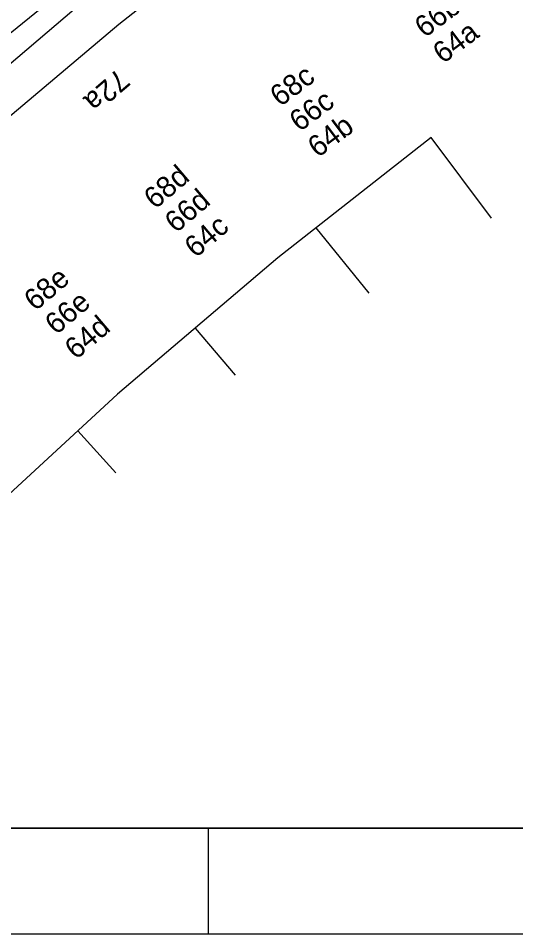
# Model space of a CAD drawing. Extents: x 81065 to 81486, y 452384 to 452681.
# Drawn here: x 81161.34 to 81184.88, y 452383.53 to 452426.85 of the extents above; entities that cross this region are included whole.
import ezdxf

# ---------------------------------------------------------------- set-up
doc = ezdxf.new("R2010")
doc.units = 0
for name, color, linetype in [('B-BH-AL-TOPOGRAFIE_HUISNUMMER-T25', 7, 'Continuous'), ('B-BH-OG-TERREIN_ERF-GV', 7, 'Continuous'), ('B-BH-OG-TOPOGRAFIE_BEBOUWING-GV', 7, 'Continuous'), ('B-BH-VH-KANTOPSLUITING-GV', 7, 'Continuous'), ('X-XX-AL-TEKENBLAD_KADER-G', 7, 'Continuous'), ('X-XX-AL-TEKENBLAD_KADER_AFSNIJMARKERING-G', 7, 'Continuous'), ('X-XX-AL-TEKENBLAD_KADER_VOUWMERK-G', 7, 'Continuous'), ('X-XX-AL-TEKENBLAD_VIEWPORT-G', 7, 'Continuous')]:
    doc.layers.add(name, color=color, linetype=linetype)

msp = doc.modelspace()

# ---------------------------------------------------------------- linework, layer by layer
at = {"layer": 'B-BH-OG-TERREIN_ERF-GV'}
for p, q in [((81177.939, 452413.843), (81175.442, 452416.944)), ((81169.709, 452412.189), (81171.601, 452409.957)), ((81165.948, 452405.341), (81164.153, 452407.332))]:
    msp.add_line(p, q, dxfattribs=at)
at = {"layer": 'B-BH-OG-TOPOGRAFIE_BEBOUWING-GV'}
msp.add_line((81183.742, 452417.4), (81180.883, 452421.217), dxfattribs=at)
for points in [[(81126.018, 452388.532), (81127.195, 452390.075), (81135.264, 452399.653), (81142.254, 452407.263), (81142.332, 452407.331), (81145.191, 452410.261), (81152.12, 452416.954), (81156.495, 452420.925), (81163.982, 452427.288), (81169.073, 452431.334), (81177.002, 452437.212), (81179.582, 452438.967)], [(81153.251, 452396.796), (81151.969, 452398.03), (81148.503, 452394.479), (81139.858, 452400.091), (81144.562, 452405.184), (81143.704, 452406.025), (81150.532, 452412.867), (81157.636, 452419.422), (81158.509, 452420.19), (81166.091, 452426.576), (81171.032, 452430.467), (81180.823, 452437.684), (81181.948, 452438.481)], [(81180.883, 452421.217), (81173.621, 452415.514), (81166.038, 452409.069), (81160.256, 452403.741), (81153.266, 452396.81), (81153.251, 452396.796)]]:
    msp.add_lwpolyline(points, dxfattribs=at)
at = {"layer": 'B-BH-VH-KANTOPSLUITING-GV'}
msp.add_lwpolyline([(81143.534, 452410.094), (81147.299, 452413.851), (81154.435, 452420.535), (81160.019, 452425.401), (81167.617, 452431.556), (81172.763, 452435.453), (81178.135, 452439.264)], dxfattribs=at)
at = {"layer": 'X-XX-AL-TEKENBLAD_KADER-G'}
msp.add_lwpolyline([(81480.708, 452388.532), (81070.22, 452388.532), (81070.22, 452675.532), (81480.708, 452675.532)], close=True, dxfattribs=at)
at = {"layer": 'X-XX-AL-TEKENBLAD_KADER_AFSNIJMARKERING-G'}
msp.add_lwpolyline([(81485.714, 452680.532), (81065.214, 452680.532), (81065.214, 452383.532), (81485.714, 452383.532)], close=True, dxfattribs=at)
at = {"layer": 'X-XX-AL-TEKENBLAD_KADER_VOUWMERK-G'}
msp.add_line((81170.339, 452383.532), (81170.339, 452388.532), dxfattribs=at)
at = {"layer": 'X-XX-AL-TEKENBLAD_VIEWPORT-G'}
msp.add_lwpolyline([(81070.22, 452388.532), (81480.708, 452388.532), (81480.708, 452675.532), (81070.22, 452675.532)], close=True, dxfattribs=at)

# ---------------------------------------------------------------- texts
at = {"layer": 'B-BH-AL-TOPOGRAFIE_HUISNUMMER-T25'}
for s, rotation, p in [('66b', 36.9, (81180.577, 452425.898)), ('64a', 36.9, (81181.44, 452424.671)), ('72a', 220.5817, (81166.057, 452424.516)), ('68c', 36.9, (81173.731, 452422.634)), ('66c', 36.9, (81174.65, 452421.449)), ('64b', 36.9, (81175.517, 452420.223)), ('68d', 40.3497, (81167.814, 452417.782)), ('66d', 40.3497, (81168.803, 452416.654)), ('64c', 40.3497, (81169.736, 452415.478)), ('68e', 40.3497, (81162.142, 452412.963)), ('66e', 40.3497, (81163.131, 452411.836)), ('64d', 40.3497, (81164.067, 452410.662))]:
    msp.add_text(s, height=1, rotation=rotation, dxfattribs=at).set_placement(p)

doc.saveas('drawing.dxf')
